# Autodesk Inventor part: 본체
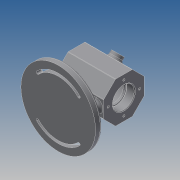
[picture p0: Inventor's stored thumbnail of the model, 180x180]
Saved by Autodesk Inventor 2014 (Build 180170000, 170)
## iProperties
Created: 2017-06
Part Number: 본체
Material: Generic
Document SubType Name: Modeling
Designer: 부인급구
Density: 1 g/cm^3
Appearance: Default
Author: 부인급구
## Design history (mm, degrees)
sketch "스케치1"
  geometry: C1 r 55 at (0, 0); 1 further point
  constraints: 1 centre point, 1 coincident
  dimensions: "d0" = 110 diameter of C1
extrude "돌출1" new body sketch "스케치1" distance "d1" = 10; taper "d2" = 0 deg
sketch "스케치2"
  geometry: L1 (0, 0)-(0, 48); L2 (30.406, -30.406)-(-33.941, 33.941); L3 (-30.406, -30.406)-(33.941, 33.941); C1 r 55 at (0, 0) reference; A1 r 5 centre (-30.406, 30.406) between (-26.87, 26.87) and (-33.73, 26.67); A2 r 5 centre (30.406, 30.406) between (26.87, 26.87) and (33.73, 26.67); A3 r 5 centre (30.406, -30.406) between (26.87, -26.87) and (33.73, -26.67); A4 r 5 centre (-30.406, -30.406) between (-26.87, -26.87) and (-33.73, -26.67); A5 r 38 centre (0, 0) between (-26.87, -26.87) and (26.87, -26.87); A6 r 38 centre (0, 0) between (26.87, 26.87) and (-26.87, 26.87); A7 r 43 centre (0, 0) between (-33.73, -26.67) and (33.73, -26.67); A8 r 43 centre (0, 0) between (33.73, 26.67) and (-33.73, 26.67); A9 r 48 centre (0, 0) between (33.941, 33.941) and (-33.941, 33.941); A10 r 48 centre (0, 0) between (-33.941, -33.941) and (33.941, -33.941)
  constraints: 30 point on circle, 10 centre point, 6 end point, 5 coincident, 4 point on line, 3 vertical alignment, 1 vertical
  dimensions: "d6" = 45 deg angle of L1 L2; "d7" = 90 deg angle of L3 L2; "d8" = 5 radius of A1; "d11" = 5 radius of A2; "d12" = 5 radius of A3; "d14" = 5 radius of A4; "d15" = 30.40559 horizontal distance of C1.centre A1.centre; "d16" = 3.53553 horizontal distance of A1.centre A1.start
extrude "돌출2" cut sketch "스케치2" distance "d17" = 3; taper "d18" = 0 deg
sketch "스케치3"
  geometry: A1 r 5 centre (-30.406, 30.406) between (-33.941, 33.941) and (-26.87, 26.87) reference; A2 r 38 centre (0, 0) between (26.87, 26.87) and (-26.87, 26.87) reference; A3 r 5 centre (30.406, 30.406) between (26.87, 26.87) and (33.941, 33.941) reference; A4 r 48 centre (0, 0) between (33.941, 33.941) and (-33.941, 33.941) reference; A5 r 5 centre (30.406, -30.406) between (33.941, -33.941) and (26.87, -26.87) reference; A6 r 38 centre (0, 0) between (-26.87, -26.87) and (26.87, -26.87) reference; A7 r 5 centre (-30.406, -30.406) between (-26.87, -26.87) and (-33.941, -33.941) reference; A8 r 48 centre (0, 0) between (-33.941, -33.941) and (33.941, -33.941) reference; A9 r 2 centre (-30.406, 30.406) between (-31.82, 31.82) and (-28.991, 28.991); A10 r 41 centre (0, 0) between (28.991, 28.991) and (-28.991, 28.991); A11 r 2 centre (30.406, 30.406) between (28.991, 28.991) and (31.82, 31.82); A12 r 45 centre (0, 0) between (31.82, 31.82) and (-31.82, 31.82); A13 r 2 centre (30.406, -30.406) between (31.82, -31.82) and (28.991, -28.991); A14 r 45 centre (0, 0) between (-31.82, -31.82) and (31.82, -31.82); A15 r 2 centre (-30.406, -30.406) between (-28.991, -28.991) and (-31.82, -31.82); A16 r 41 centre (0, 0) between (-28.991, -28.991) and (28.991, -28.991)
  constraints: 16 point on circle, 8 centre point, 6 other
  dimensions: "d19" = 2 radius of A15; "d20" = 2 radius of A9
extrude "돌출3" cut sketch "스케치3" stored distance "d21" = 3; taper "d22" = 0 deg
sketch "스케치4" dims "d23" = 60
  geometry: L1 (92, -12.426)-(74.426, -30); L2 (74.426, -30)-(49.574, -30); L3 (49.574, -30)-(32, -12.426); L4 (32, -12.426)-(32, 12.426); L5 (32, 12.426)-(49.574, 30); L6 (49.574, 30)-(74.426, 30); L7 (74.426, 30)-(92, 12.426); L8 (92, 12.426)-(92, -12.426); L9 (0, 55)-(0, -55) reference; 5 further points
  constraints: 16 end point, 3 horizontal alignment, 2 midpoint, 1 coincident, 19 other
  dimensions: "d24" = 62 distance from line of L9 point (62, 0)
extrude "돌출4" join sketch "스케치4" stored distance "d25" = 70; taper "d26" = 0 deg
sketch "스케치5"
  geometry: L1 (-24, 5)-(24, 5); L2 (24, 5)-(24, -5); L3 (24, -5)-(-24, -5); L4 (-24, -5)-(-24, 5); L5 (24, -5)-(-24, 5); C1 r 5 at (-24, 0); C2 r 5 at (24, 0); A1 r 38 centre (0, 0) between (-26.87, -26.87) and (26.87, -26.87) reference; 1 further point
  constraints: 10 end point, 3 midpoint, 2 centre point, 2 parallel, 1 coincident, 1 horizontal, 1 perpendicular
  dimensions: "d27" = 48 distance of L1.start L1.end; "d28" = 10 distance of L3.end L1.start; "d29" = 5 radius of C1; "d30" = 5 radius of C2
extrude "돌출5" join sketch "스케치5" stored distance "d31" = 70; taper "d32" = 0 deg
sketch "스케치6"
  geometry: L1 (0, 0)-(0, 24.853) reference; L2 (70, 42.426)-(0, 42.426) reference; 2 further points
  constraints: 1 other
  dimensions: "d33" = 35 distance from line of L1 point (35, 12.426); "d34" = 30 distance from line of L2 point (35, 12.426)
feature "엠보싱1" sketch "스케치6" dims "d6" = 45 deg, "d7" = 90 deg, "d8" = 5, "d11" = 5, "d12" = 5, "d14" = 5, "d15" = 30.40559, "d16" = 3.53553, "d35" = 0.5, "d36" = 0
sketch "스케치7"
  geometry: L1 (74.426, -30)-(92, -12.426) reference; L2 (92, -12.426)-(92, 12.426) reference; L3 (92, 12.426)-(74.426, 30) reference; L4 (74.426, 30)-(49.574, 30) reference; L5 (49.574, 30)-(32, 12.426) reference; L6 (32, 12.426)-(32, -12.426) reference; L7 (32, -12.426)-(49.574, -30) reference; L8 (49.574, -30)-(74.426, -30) reference; L9 (62, 50)-(62, -50); L10 (0, 55)-(0, -55) reference; L11 (62, 0)-(83.213, 21.213); 2 further points
  constraints: 4 end point, 3 midpoint, 1 horizontal alignment, 1 perpendicular
  dimensions: "d37" = 62 distance between parallel lines of L10 L9; "d38" = 45 deg angle of L9 L11
  node "투영된 루프2"
node "작업 평면1"
sketch "스케치8"
  geometry: C1 r 8 at (0, 0); 2 further points
  constraints: 1 centre point, 1 coincident
  dimensions: "d39" = 16 diameter of C1
extrude "돌출6" join sketch "스케치8" distance "d40" = 7; taper "d41" = 0 deg
sketch "스케치9"
  geometry: L1 (-55, 0)-(55, 0) reference; C1 r 16 at (0, 62); 2 further points
  constraints: 1 centre point, 1 midpoint, 1 vertical alignment
  dimensions: "d42" = 32 diameter of C1; "d43" = 62 distance from line of L1 C1.centre
extrude "돌출7" cut sketch "스케치9" distance "d44" = 12; taper "d45" = 0 deg
sketch "스케치10"
  geometry: C1 r 16 at (0, 0) reference; C2 r 14 at (0, 0); 1 further point
  constraints: 1 centre point, 1 coincident
  dimensions: "d46" = 28 diameter of C2
extrude "돌출8" cut sketch "스케치10" distance "d47" = 3; taper "d48" = 0 deg
sketch "스케치11"
  geometry: C1 r 14 at (0, 0) reference; C2 r 25 at (0, 0); 1 further point
  constraints: 1 centre point, 1 coincident
  dimensions: "d49" = 50 diameter of C2
extrude "돌출9" cut sketch "스케치11" distance "d50" = 40; taper "d51" = 0 deg
sketch "스케치12"
  geometry: C1 r 25 at (0, 0) reference; C2 r 14 at (0, 0); 1 further point
  constraints: 1 centre point, 1 coincident
  dimensions: "d52" = 28 diameter of C2
extrude "돌출10" cut sketch "스케치12" distance "d53" = 3; taper "d54" = 0 deg
sketch "스케치13"
  geometry: C1 r 14 at (0, 0) reference; C2 r 16 at (0, 0); 1 further point
  constraints: 1 centre point, 1 coincident
  dimensions: "d55" = 32 diameter of C2
extrude "돌출11" cut sketch "스케치13" distance "d56" = 12; taper "d57" = 0 deg
sketch "스케치14"
  geometry: C1 r 8 at (0, 0) reference; C2 r 4 at (0, 0); 1 further point
  constraints: 1 centre point, 1 coincident
  dimensions: "d58" = 8 diameter of C2
extrude "돌출12" cut sketch "스케치14" stored distance "d59" = 12; taper "d60" = 0 deg
sketch "스케치15" dims "d61" = 46
  geometry: L1 (12.426, 92)-(-12.426, 92) reference; L2 (0, 62)-(0, 85); C1 r 16 at (0, 62) reference; 2 further points
  constraints: 2 coincident, 2 end point, 1 perpendicular, 1 vertical alignment, 2 other
hole "구멍1" sketch "스케치15" at (0, 85) diameter "d62" = 3.242; stored, may be unused: countersink angle "d66" = 90 deg, drill point angle "d68" = 118 deg; dims "d63" = 8, "d64" = 4, "d65" = 2, "d67" = 10
fillet "모깎기1" dims "d72" = 0.3
fillet "모깎기2" dims "d73" = 1
fillet "모깎기3" dims "d74" = 3
fillet "모깎기4" dims "d75" = 5
chamfer "모따기1" distance "d76" = 1; stored, may be unused: second distance "d77" = 2, angle "d78" = 45 deg
node "솔리드1"
pattern_circular "원형 패턴1" dims angle "d70" = 360 deg
mirror "대칭1"
node "투영된 루프1"
other parameters: "d3" = 96, "d4" = 76, "d5" = 86
